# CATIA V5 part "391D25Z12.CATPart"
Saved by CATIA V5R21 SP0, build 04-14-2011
Part number: 391D25Z12
Bounding box of the stored display mesh (mm): x -48.732 to 48.732, y -12 to 12, z -48.732 to 48.732
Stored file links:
  C:\Users\ALI OZGUN\Desktop\alhan\TESLIMEDILEN3\391D25Z12.CATPart
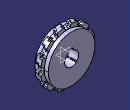
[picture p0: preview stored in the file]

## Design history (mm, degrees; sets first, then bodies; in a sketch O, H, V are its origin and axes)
Body1 (main body)
  Sketch1 on zx-plane, origin (0, 0, 0), H (-1, 0, 0), V (0, 0, 1)
    circle A1 centre (0, 0) radius 42.25
    radius A1 = 42.25
  Pad1: profile Sketch1, direction (0, 1, 0), length 14
  Sketch2 on zx-plane, origin (0, 0, 0), H (-1, 0, 0), V (0, 0, 1)
    circle A1 centre (0, 0) radius 49
    radius A1 = 49
  Pad2: profile Sketch2, direction (0, 1, 0), length 5
  Sketch3 on end face of Pad2, origin (0, 5, 0), H (-1, 0, 0), V (0, 0, 1)
    point P1 (-6.5, 48.567)
    line L1 (-6.5, 48.567) -> (-4.25, 42.7895)
    point P2 (-4.25, 42.7895)
    arc A1 centre (0, 0) radius 43 from (4.25, 42.7895) to (-4.25, 42.7895) ccw
    reference projected circle E1 centre (0, 0) radius 49 from edge [face of Pad2 from Sketch2.A1 | end face of Pad2]
    point P3 (4.25, 42.7895)
    point P4 (6.5, 48.567)
    line L2 (6.5, 48.567) -> (4.25, 42.7895)
    radius A1 = 43
    distance P1 V = 6.5
    distance P2 V = 4.25
    coincidence: P1 E1
    symmetry: P2 P3 V, P1 P4 V, L1 L2 V
  Pocket1: profile Sketch3, direction (0, -1, 0), length 5
  CircPattern1: of Pocket1, instances 12, angular step 30, axis from face of Pad1 from Sketch1.A1
  Fillet1: radius 2, on edge [face of CircPattern1 | face of Pad2 from Sketch2.A1] (x11); edge [face of Pad2 from Sketch2.A1 | face of CircPattern1] (x11); edge [face of Pocket1 from Sketch3.L1 | face of Pad2 from Sketch2.A1]; edge [face of Pad2 from Sketch2.A1 | face of Pocket1 from Sketch3.L2]; edge [face of CircPattern1 | face of CircPattern1] (x22); edge [face of Pocket1 from Sketch3.L2 | face of Pocket1 from Sketch3.A1]; edge [face of Pocket1 from Sketch3.A1 | face of Pocket1 from Sketch3.L1]
Body2
  Solid1: linked copy from another document
  Body3
    Solid2: linked copy from another document
    Symmetry1: ToTransfor Solid2, Reference face of Solid2
    Rotate1: Axis Sketch4, Angle 3.5, ToTransfor Symmetry1
    Sketch4 on yz-plane, origin (0, 0, 0), H (0, 1, 0), V (0, 0, 1)
      line L1 (68.9983, 0) -> (-60.7772, 0)
      point P1 (68.9983, 0)
      coincidence: P1 H
      horizontal: L1 H
  Add1: tool Body3
  Sketch5 on face of Solid1, origin (0, 14, 0), H (-1, 0, 0), V (0, 0, 1)
    arc A1 centre (0, 0) radius 12.5 from (-4, 11.8427) to (4, 11.8427) ccw
    line L1 (4, 15.8427) -> (-4, 15.8427)
    line L2 (-4, 15.8427) -> (-4, 11.8427)
    line L3 (4, 11.8427) -> (4, 15.8427)
    length L2 = 4
    length L1 = 8
    radius A1 = 12.5
    distance L3 V = 4
    horizontal: L1 H
    vertical: L2 V, L3 V
  Pocket2: profile Sketch5, direction (0, -1, 0), through (limit type 6)
  Sketch6 on face of Solid1, origin (0, 14, 0), H (-1, 0, 0), V (0, 0, 1)
    construction line L1 (-18.4923, 18.4923) -> (16.4725, -16.4725)
    axis line L2 (23.8397, 23.8397) -> (-21.8636, -21.8636)
    construction circle A1 centre (0, 0) radius 13.5
    arc A2 centre (-7.3058, -7.3058) radius 17 from (-9.5459, 9.5459) to (0, 8.0443) cw
    point P6 (-9.5459, 9.5459)
    point P7 (9.5459, -9.5459)
    point P8 (4.715, 4.715)
    point P9 (9.5459, -9.5459)
    point P10 (-9.5459, 9.5459)
    arc A3 centre (7.3058, 7.3058) radius 17 from (-9.5459, 9.5459) to (-8.0443, 0) ccw
    point P12 (-9.5459, -9.5459)
    point P13 (9.5459, 9.5459)
    arc A4 centre (-7.3058, 7.3058) radius 17 from (9.5459, 9.5459) to (8.0443, 0) cw
    point P15 (-9.5459, -9.5459)
    point P16 (9.5459, 9.5459)
    arc A5 centre (7.3058, -7.3058) radius 17 from (9.5459, 9.5459) to (0, 8.0443) ccw
    arc A6 centre (7.3058, -7.3058) radius 17 from (-8.0443, 0) to (-9.5459, -9.5459) ccw
    arc A7 centre (7.3058, 7.3058) radius 17 from (0, -8.0443) to (9.5459, -9.5459) ccw
    arc A8 centre (-7.3058, 7.3058) radius 17 from (0, -8.0443) to (-9.5459, -9.5459) cw
    point P20 (8.0443, 0)
    arc A9 centre (-7.3058, -7.3058) radius 17 from (8.0443, 0) to (9.5459, -9.5459) cw
    angle L1 V = 45
    angle V L2 = 45
    radius A1 = 13.5
    radius A2 = 17
    coincidence: L1 O, L2 O, P6 A1, P6 L1, P7 A1, P7 L1, A2 P8, P8 L2, A5 A6, A3 A7, A4 A8, A2 P20, A2 A9, P6 P10, P7 P9, P12 P15, P13 P16
    symmetry: P7 P9 L1, P6 P10 L1, A2 A3 L1, P9 P12 V, P10 P13 V, A3 A4 V, P7 P15 V, P6 P16 V, A2 A5 V
  Pocket3: profile Sketch6, direction (0, -1, 0), through (limit type 6)
  Thickness1: Face (face of Solid2; face of Solid1), Thickness -2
